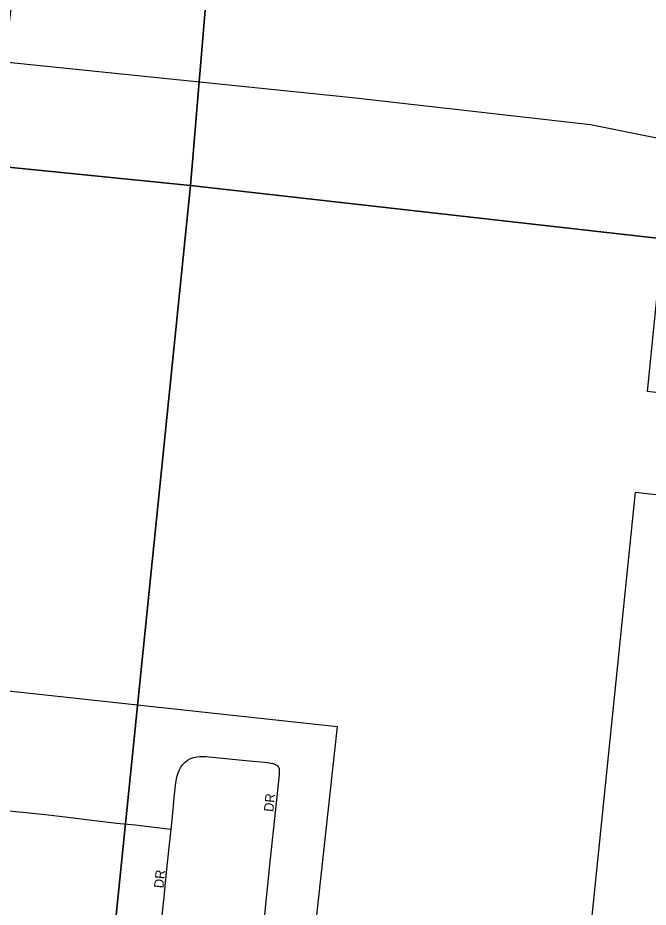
# Model space of a CAD drawing. Extents: x -209 to 4852, y 0 to 905.
# Drawn here: x 165.41 to 177.93, y 235.21 to 252.89 of the extents above; entities that cross this region are included whole.
import ezdxf

# ---------------------------------------------------------------- set-up
doc = ezdxf.new("R2010")
doc.units = 0
for name, color, linetype in [('GM_X_County_ROW', 7, 'Continuous'), ('GM_X_Interstate_Location', 7, 'Continuous'), ('GM_X_Minor_River', 7, 'Continuous'), ('GM_X_Township_Text', 7, 'Continuous'), ('GM_X_US_Location', 7, 'Continuous')]:
    doc.layers.add(name, color=color, linetype=linetype)

msp = doc.modelspace()

# ---------------------------------------------------------------- linework, layer by layer
at = {"layer": 'GM_X_County_ROW'}
msp.add_lwpolyline([(163.183, 237.354), (163.306, 237.339), (163.803, 237.282), (164.726, 237.183), (165.154, 237.136), (165.511, 237.101), (165.957, 237.053), (166.569, 236.98), (166.774, 236.955), (167.366, 236.884), (167.737, 236.848), (168.009, 236.818), (168.386, 236.771), (168.457, 236.762)], dxfattribs=at)
at = {"layer": 'GM_X_Minor_River'}
for points in [[(149.411, 271.455), (170.498, 269.384), (168.839, 249.556), (147.511, 251.706)], [(170.498, 269.384), (189.771, 267.627), (187.727, 247.423), (168.839, 249.556)], [(147.511, 251.706), (168.839, 249.556), (166.746, 229.007), (145.448, 231.165)], [(168.839, 249.556), (187.727, 247.423), (185.611, 227.061), (166.746, 229.007)]]:
    msp.add_lwpolyline(points, close=True, dxfattribs=at)
at = {"layer": 'GM_X_Township_Text'}
for points in [[(168.457, 236.762), (168.485, 237.018), (168.518, 237.388), (168.541, 237.636), (168.558, 237.761), (168.573, 237.823), (168.593, 237.883), (168.618, 237.942), (168.649, 237.998), (168.686, 238.05), (168.731, 238.098), (168.783, 238.137), (168.841, 238.166), (168.902, 238.186), (168.964, 238.2), (169.028, 238.208), (169.091, 238.21), (169.154, 238.207), (169.204, 238.203), (169.277, 238.196), (170.004, 238.123), (170.319, 238.093), (170.445, 238.076), (170.476, 238.068), (170.505, 238.058), (170.532, 238.044), (170.558, 238.026), (170.581, 238.004), (170.592, 237.986), (170.599, 237.971)], [(170.224, 234.183), (170.229, 234.263), (170.317, 235.069), (170.42, 236.117), (170.535, 237.164), (170.602, 237.781), (170.606, 237.842), (170.61, 237.905), (170.607, 237.938), (170.604, 237.955), (170.599, 237.971)], [(168.164, 233.936), (168.206, 234.367), (168.255, 234.858), (168.294, 235.23), (168.313, 235.414), (168.365, 235.907), (168.391, 236.154), (168.418, 236.401), (168.457, 236.762)]]:
    msp.add_lwpolyline(points, dxfattribs=at)
at = {"layer": 'GM_X_US_Location'}
for points in [[(179.024, 250.316), (176.783, 250.762), (172.058, 251.298), (165.143, 252.007), (166.158, 260.117), (167.538, 259.958), (169.05, 259.804), (169.781, 259.743), (169.739, 259.269), (172.993, 258.926), (173.196, 260.851), (174.989, 260.672), (175.107, 261.574), (173.726, 262.205), (173.252, 262.423), (172.128, 262.942), (171.218, 263.373), (168.956, 264.498), (169.655, 272.234), (173.556, 272.158), (174.047, 272.12), (177.365, 271.98), (177.371, 271.893), (181.093, 271.889)], [(145.512, 231.298), (146.106, 237.815), (147.24, 237.665), (150.613, 235.875), (151.83, 240.074), (151.933, 240.906), (154.828, 240.564), (155.138, 243.402), (151.621, 243.764), (151.833, 245.855), (157.701, 245.278), (157.764, 245.944), (158.163, 250.081), (158.193, 250.508), (158.23, 251.005), (158.305, 251.869), (158.394, 252.832), (165.096, 251.97), (163.466, 241.622), (163.571, 239.69), (171.755, 238.803), (170.95, 231.479)], [(185.425, 244.558), (177.919, 245.465), (178.217, 248.43)], [(182.713, 234.455), (176.82, 235.041), (177.681, 243.465), (184.857, 242.643)]]:
    msp.add_lwpolyline(points, dxfattribs=at)

# ---------------------------------------------------------------- texts
at = {"layer": 'GM_X_Interstate_Location'}
for p in [(170.483, 237.1), (168.3, 235.583)]:
    msp.add_text('DR', height=0.1894, rotation=83.9826, dxfattribs=at).set_placement(p)

doc.saveas('drawing.dxf')
